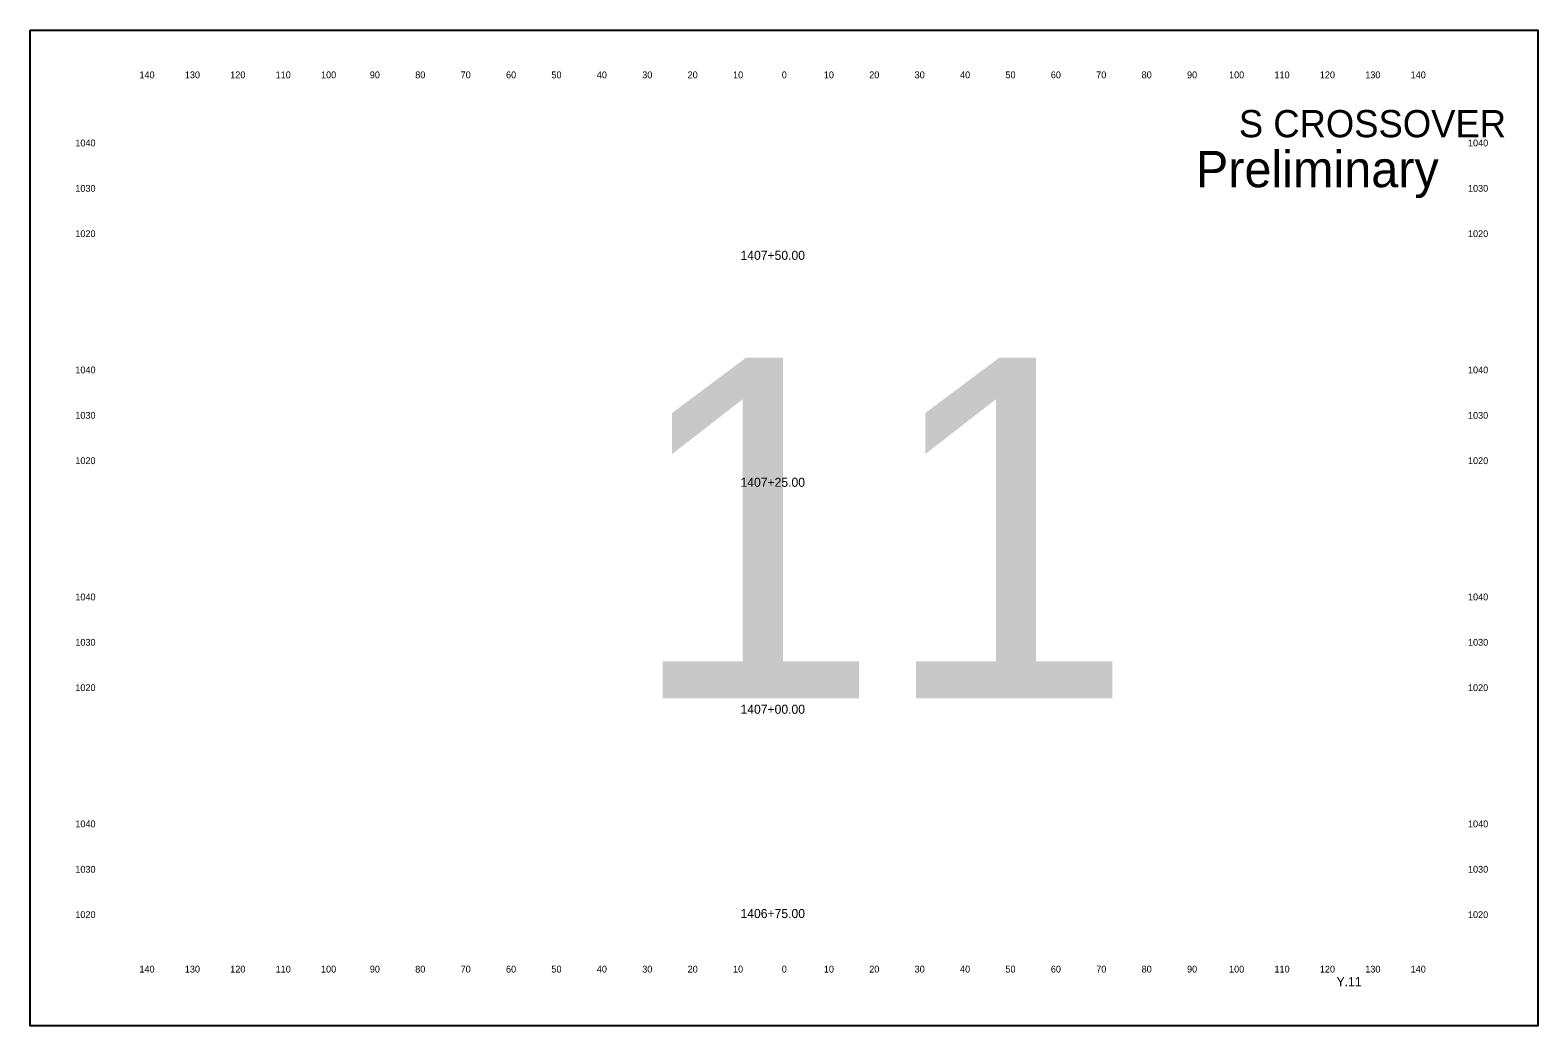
# Model space of a CAD drawing. Extents: x 10123 to 14768, y 9730 to 9950.
# Drawn here: x 13723.2 to 14055.3, y 9730.3 to 9949.6 of the extents above; entities that cross this region are included whole.
import ezdxf

# ---------------------------------------------------------------- set-up
doc = ezdxf.new("R2010")
doc.units = 0
for name, color, linetype in [('dsnTextCpn', 7, 'Continuous'), ('dsnTextCpnTitleSheetLocDesc', 7, 'Continuous'), ('dsnTextCpnTitleSheetPIN', 7, 'Continuous'), ('dsnTextCpnTitleSheetWorkType', 7, 'Continuous')]:
    doc.layers.add(name, color=color, linetype=linetype)

msp = doc.modelspace()

# ---------------------------------------------------------------- linework, layer by layer
at = {"layer": 'dsnTextCpnTitleSheetWorkType'}
msp.add_lwpolyline([(13723.21, 9949.6), (14055.29, 9949.6), (14055.29, 9730.26), (13723.21, 9730.26)], close=True, dxfattribs=at)

# ---------------------------------------------------------------- texts
at = {"layer": 'dsnTextCpn'}
for s, height, p in [('140', 1.5, (13747.27, 9939)), ('130', 1.5, (13757.27, 9939)), ('120', 1.5, (13767.27, 9939)), ('110', 1.5, (13777.27, 9939)), ('100', 1.5, (13787.27, 9939)), ('90', 1.5, (13798.02, 9939)), ('80', 1.5, (13808.02, 9939)), ('70', 1.5, (13818.02, 9939)), ('60', 1.5, (13828.02, 9939)), ('50', 1.5, (13838.02, 9939)), ('40', 1.5, (13848.02, 9939)), ('30', 1.5, (13858.02, 9939)), ('20', 1.5, (13868.02, 9939)), ('10', 1.5, (13878.02, 9939)), ('0', 1.5, (13888.76, 9939)), ('0', 1.5, (13888.76, 9939)), ('10', 1.5, (13898.02, 9939)), ('20', 1.5, (13908.02, 9939)), ('30', 1.5, (13918.02, 9939)), ('40', 1.5, (13928.02, 9939)), ('50', 1.5, (13938.02, 9939)), ('60', 1.5, (13948.02, 9939)), ('70', 1.5, (13958.02, 9939)), ('80', 1.5, (13968.02, 9939)), ('90', 1.5, (13978.02, 9939)), ('100', 1.5, (13987.27, 9939)), ('110', 1.5, (13997.27, 9939)), ('120', 1.5, (14007.27, 9939)), ('130', 1.5, (14017.27, 9939)), ('140', 1.5, (14027.27, 9939)), ('S CROSSOVER', 6, (13989.44, 9926)), ('1040', 1.5, (13733.15, 9924)), ('1040', 1.5, (14039.9, 9924)), ('1030', 1.5, (13733.15, 9914)), ('1030', 1.5, (14039.9, 9914)), ('1020', 1.5, (13733.15, 9904)), ('1020', 1.5, (14039.9, 9904)), ('1407+50.00', 2, (13879.67, 9899)), ('1040', 1.5, (13733.15, 9874)), ('1040', 1.5, (14039.9, 9874)), ('1030', 1.5, (13733.15, 9864)), ('1030', 1.5, (14039.9, 9864)), ('1020', 1.5, (13733.15, 9854)), ('1020', 1.5, (14039.9, 9854)), ('1407+25.00', 2, (13879.67, 9849)), ('1040', 1.5, (13733.15, 9824)), ('1040', 1.5, (14039.9, 9824)), ('1030', 1.5, (13733.15, 9814)), ('1030', 1.5, (14039.9, 9814)), ('1020', 1.5, (13733.15, 9804)), ('1020', 1.5, (14039.9, 9804)), ('1407+00.00', 2, (13879.67, 9799)), ('1040', 1.5, (13733.15, 9774)), ('1040', 1.5, (14039.9, 9774)), ('1030', 1.5, (13733.15, 9764)), ('1030', 1.5, (14039.9, 9764)), ('1020', 1.5, (13733.15, 9754)), ('1406+75.00', 2, (13879.67, 9754)), ('1020', 1.5, (14039.9, 9754)), ('140', 1.5, (13747.27, 9742)), ('130', 1.5, (13757.27, 9742)), ('120', 1.5, (13767.27, 9742)), ('110', 1.5, (13777.27, 9742)), ('100', 1.5, (13787.27, 9742)), ('90', 1.5, (13798.02, 9742)), ('80', 1.5, (13808.02, 9742)), ('70', 1.5, (13818.02, 9742)), ('60', 1.5, (13828.02, 9742)), ('50', 1.5, (13838.02, 9742)), ('40', 1.5, (13848.02, 9742)), ('30', 1.5, (13858.02, 9742)), ('20', 1.5, (13868.02, 9742)), ('10', 1.5, (13878.02, 9742)), ('0', 1.5, (13888.76, 9742)), ('0', 1.5, (13888.76, 9742)), ('10', 1.5, (13898.02, 9742)), ('20', 1.5, (13908.02, 9742)), ('30', 1.5, (13918.02, 9742)), ('40', 1.5, (13928.02, 9742)), ('50', 1.5, (13938.02, 9742)), ('60', 1.5, (13948.02, 9742)), ('70', 1.5, (13958.02, 9742)), ('80', 1.5, (13968.02, 9742)), ('90', 1.5, (13978.02, 9742)), ('100', 1.5, (13987.27, 9742)), ('110', 1.5, (13997.27, 9742)), ('120', 1.5, (14007.27, 9742)), ('130', 1.5, (14017.27, 9742)), ('140', 1.5, (14027.27, 9742))]:
    msp.add_text(s, height=height, dxfattribs=at).set_placement(p)
at = {"layer": 'dsnTextCpnTitleSheetLocDesc'}
msp.add_text('Preliminary', height=8, dxfattribs=at).set_placement((13979.97, 9915))
at = {"layer": 'dsnTextCpnTitleSheetPIN'}
msp.add_text('Y.11', height=2, dxfattribs=at).set_placement((14010.96, 9739))
at = {"layer": 'dsnTextCpnTitleSheetWorkType'}
msp.add_text('11', height=75, dxfattribs=at).set_placement((13854.92, 9802.43))

doc.saveas('drawing.dxf')
